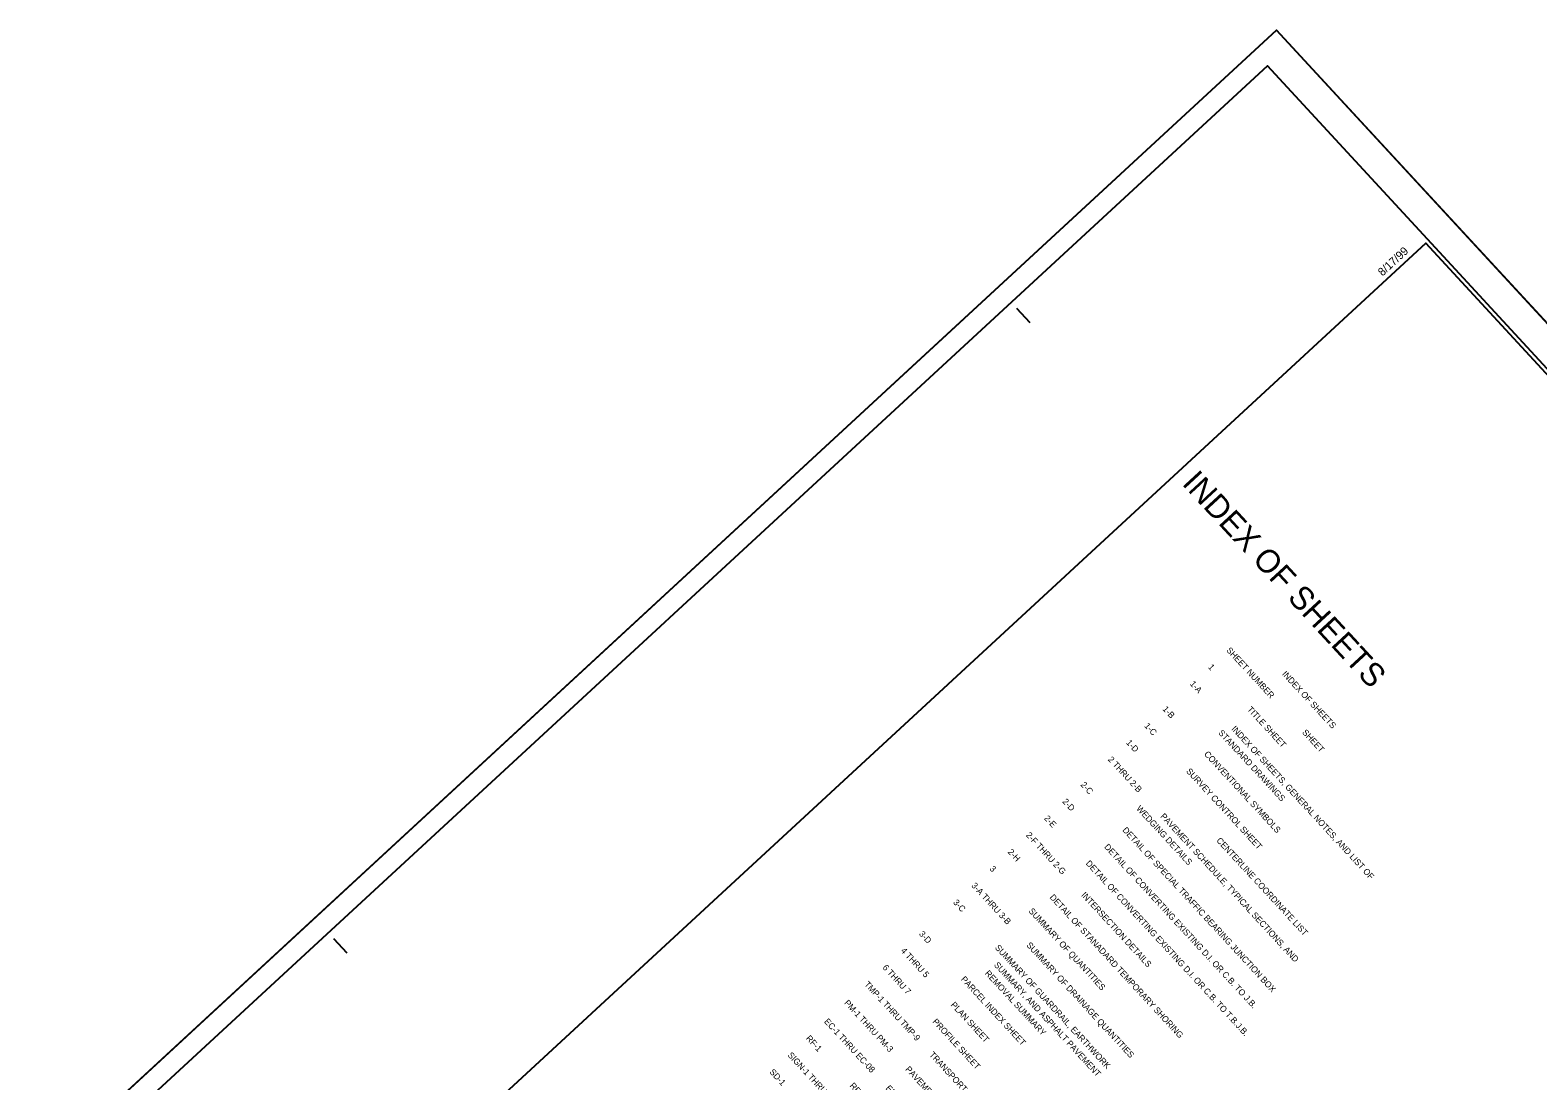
# Model space of a CAD drawing. Extents: x 1695041 to 1706254, y 786537 to 798223.
# Drawn here: x 1695041 to 1696988, y 796480 to 797836 of the extents above; entities that cross this region are included whole.
import ezdxf

# ---------------------------------------------------------------- set-up
doc = ezdxf.new("R2010")
doc.units = 0
for name, color, linetype in [('Old_Level_16', 7, 'Continuous'), ('Old_Level_23', 7, 'Continuous'), ('Sheet Cutting Line CELL', 7, 'Continuous'), ('Sheet Plan CELL', 7, 'Continuous'), ('Sheet Plot Border Inside CELL', 7, 'Continuous'), ('Sheet Plot Border Outside CELL', 7, 'Continuous')]:
    doc.layers.add(name, color=color, linetype=linetype)

msp = doc.modelspace()

# ---------------------------------------------------------------- linework, layer by layer
at = {"layer": 'Sheet Cutting Line CELL'}
for p, q in [((1696650.4, 797836.1), (1695041.2, 796350.7)), ((1698934.2, 795362), (1696650.4, 797836.1))]:
    msp.add_line(p, q, dxfattribs=at)
at = {"layer": 'Sheet Plan CELL'}
for p, q in [((1696843.2, 797560.9), (1696843.2, 797560.9)), ((1696314.8, 797477.3), (1696331.8, 797458.9)), ((1695433, 796663.4), (1695450, 796645))]:
    msp.add_line(p, q, dxfattribs=at)
msp.add_lwpolyline([(1698878.1, 795356.5), (1696843.2, 797560.9), (1695300.2, 796136.5), (1697335, 793932.1)], close=True, dxfattribs=at)
at = {"layer": 'Sheet Plot Border Inside CELL'}
msp.add_lwpolyline([(1695088.2, 796358.7), (1697348.3, 793910.3), (1698898.7, 795341.5), (1696638.7, 797789.9)], close=True, dxfattribs=at)
at = {"layer": 'Sheet Plot Border Outside CELL'}
msp.add_lwpolyline([(1695041.2, 796350.7), (1697325, 793876.6), (1698934.2, 795362), (1696650.4, 797836.1)], close=True, dxfattribs=at)

# ---------------------------------------------------------------- texts
at = {"layer": 'Old_Level_16'}
msp.add_text('                        INDEX OF SHEETS ', height=30, rotation=312.7091, dxfattribs=at).set_placement((1696345.8, 797446.6))
at = {"layer": 'Old_Level_23'}
for s, p in [('SHEET NUMBER                    SHEET   ', (1696584.9, 797035.1)), ('1                       TITLE SHEET', (1696561.4, 797013.3)), ('1-A                     INDEX OF SHEETS, GENERAL NOTES, AND LIST OF ', (1696537.9, 796991.6)), ('                        INDEX OF SHEETS ', (1696608.5, 797056.8)), ('1-B                     CONVENTIONAL SYMBOLS ', (1696502.6, 796959.1)), ('1-C                     SURVEY CONTROL SHEET ', (1696479.1, 796937.4)), ('1-D           ', (1696455.6, 796915.7)), ('                        STANDARD DRAWINGS', (1696526.2, 796980.8)), ('2 THRU 2-B              PAVEMENT SCHEDULE, TYPICAL SECTIONS, AND ', (1696432.1, 796894)), ('2-C                     DETAIL OF SPECIAL TRAFFIC BEARING JUNCTION BOX', (1696396.8, 796861.4)), ('2-D                     DETAIL OF CONVERTING EXISTING D.I. OR C.B. TO J.B.', (1696373.3, 796839.7)), ('                        WEDGING DETAILS ', (1696420.3, 796883.1)), ('2-E                     DETAIL OF CONVERTING EXISTING D.I. OR C.B. TO T.B.J.B.', (1696349.8, 796818)), ('2-F THRU 2-G            INTERSECTION DETAILS', (1696326.3, 796796.3)), ('2-H                     DETAIL OF STANADARD TEMPORARY SHORING', (1696302.8, 796774.6)), ('    CENTERLINE COORDINATE LIST ', (1696564.1, 796798.1)), ('3                       SUMMARY OF QUANTITIES ', (1696279.3, 796752.9)), ('3-A THRU 3-B            SUMMARY OF DRAINAGE QUANTITIES ', (1696255.8, 796731.2)), ('3-C                     SUMMARY OF GUARDRAIL, EARTHWORK ', (1696232.2, 796709.5)), ('3-D                     PARCEL INDEX SHEET', (1696188.2, 796668.8)), ('4 THRU 5                PLAN SHEET', (1696164.6, 796647.1)), ('6 THRU 7                PROFILE SHEET  ', (1696141.1, 796625.4)), ('                                REMOVAL SUMMARY', (1696208.7, 796687.8)), ('                                SUMMARY, AND ASPHALT PAVEMENT', (1696220.5, 796698.6)), ('TMP-1 THRU TMP-9        TRANSPORTATION MANAGEMENT PLANS', (1696117.6, 796603.7)), ('PM-1 THRU PM-3          PAVEMENT MARKING PLANS', (1696091.6, 796579.7)), ('EC-1 THRU EC-08         EROSION CONTROL PLANS', (1696065.7, 796555.7)), ('RF-1                    REFORESTATION PLANS', (1696042.2, 796534)), ('SIGN-1 THRU SIGN-4      SIGNING PLANS', (1696018.6, 796512.3)), ('SD-1                    SIGNAL PLANS', (1695995.1, 796490.6))]:
    msp.add_text(s, height=8, rotation=312.7091, dxfattribs=at).set_placement(p)
at = {"layer": 'Sheet Plan CELL'}
msp.add_text('8/17/99', height=10.5, rotation=42.7091, dxfattribs=at).set_placement((1696787.1, 797517.9))

doc.saveas('drawing.dxf')
